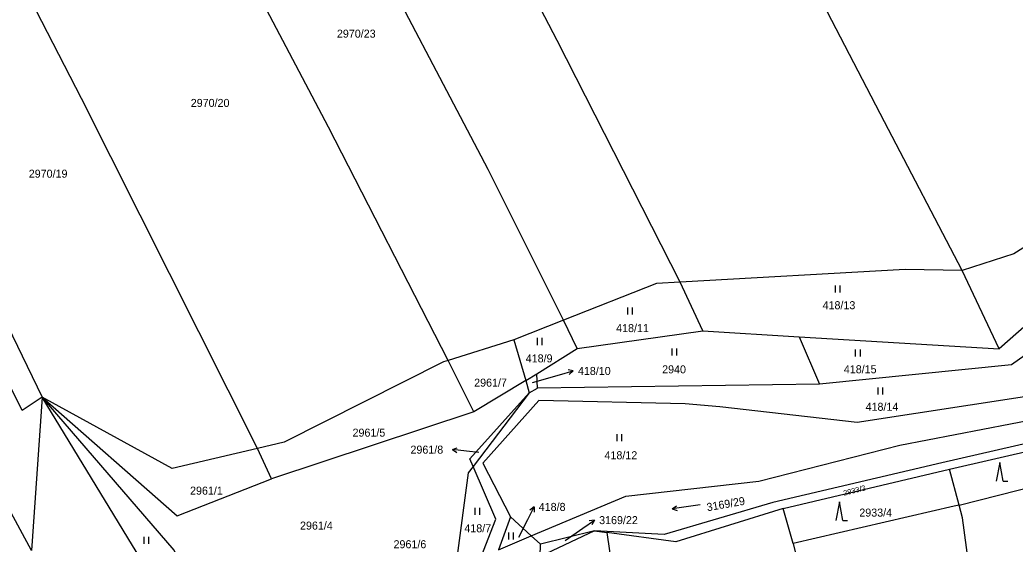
# Model space of a CAD drawing. Extents: x -776734 to -748832, y -1118122 to -976986.
# Drawn here: x -754304.9 to -754093.6, y -1113887.9 to -1113776.6 of the extents above; entities that cross this region are included whole.
import ezdxf

# ---------------------------------------------------------------- set-up
doc = ezdxf.new("R2010")
doc.units = 0
for name, color, linetype in [('KM_Hranice parcel', 7, 'Continuous'), ('KM_Parcelní čísla', 7, 'Continuous'), ('KM_Pop  PČ popisy', 7, 'Continuous'), ('KM_Značky kultur', 7, 'Continuous')]:
    doc.layers.add(name, color=color, linetype=linetype)

msp = doc.modelspace()

# ---------------------------------------------------------------- linework, layer by layer
at = {"layer": 'KM_Hranice parcel'}
for p, q in [((-754318.46, -1113819.03), (-754300.22, -1113856.73)), ((-754097, -1113846.43), (-754104.86, -1113829.84)), ((-754077.8, -1113829.36), (-754097, -1113846.43)), ((-754159.94, -1113842.59), (-754164.76, -1113832.3)), ((-754189.51, -1113840.37), (-754200.04, -1113844.53)), ((-754186.65, -1113846.37), (-754189.51, -1113840.37)), ((-754186.65, -1113846.37), (-754159.94, -1113842.59)), ((-754159.94, -1113842.59), (-754139.48, -1113843.91)), ((-754200.04, -1113844.53), (-754214.04, -1113848.92)), ((-754200.04, -1113844.53), (-754197.55, -1113853.18)), ((-754139.48, -1113843.91), (-754097, -1113846.43)), ((-754139.48, -1113843.91), (-754135.16, -1113853.97)), ((-754195.19, -1113851.76), (-754186.65, -1113846.37)), ((-754208.56, -1113859.8), (-754214.04, -1113848.92)), ((-754197.55, -1113853.18), (-754195.19, -1113851.76)), ((-754195.04, -1113854.77), (-754195.19, -1113851.76)), ((-754197.55, -1113853.18), (-754208.56, -1113859.8)), ((-754197.55, -1113853.18), (-754196.79, -1113855.81)), ((-754135.16, -1113853.97), (-754195.04, -1113854.77)), ((-754196.79, -1113855.81), (-754208.72, -1113871.43)), ((-754196.79, -1113855.81), (-754195.04, -1113854.77)), ((-754300.22, -1113856.73), (-754302.5, -1113889.3)), ((-754274.44, -1113898.95), (-754300.22, -1113856.73)), ((-754208.56, -1113859.8), (-754251.51, -1113874.03)), ((-754107.55, -1113872.02), (-754074.63, -1113864.42)), ((-754302.5, -1113889.3), (-754314.85, -1113866.35)), ((-754251.51, -1113874.03), (-754254.49, -1113867.61)), ((-754142.86, -1113880.35), (-754107.55, -1113872.02)), ((-754105.53, -1113879.61), (-754107.55, -1113872.02)), ((-754105.53, -1113879.61), (-754073.23, -1113871.5)), ((-754140.8, -1113887.79), (-754142.86, -1113880.35)), ((-754200.79, -1113882.1), (-754203.33, -1113889.11)), ((-754196.38, -1113886.18), (-754200.79, -1113882.1)), ((-754182.95, -1113885.07), (-754194.51, -1113890.52)), ((-754182.95, -1113885.07), (-754194.43, -1113887.89)), ((-754182.95, -1113885.07), (-754180.32, -1113885.43)), ((-754180.32, -1113885.43), (-754179.21, -1113893.05)), ((-754203.33, -1113889.11), (-754196.38, -1113886.18)), ((-754194.43, -1113887.89), (-754196.38, -1113886.18)), ((-754140.8, -1113887.79), (-754139.9, -1113891.23)), ((-754194.51, -1113890.52), (-754194.43, -1113887.89))]:
    msp.add_line(p, q, dxfattribs=at)
for points in [[(-754104.86, -1113829.84), (-754121.36, -1113798.21), (-754148.4, -1113746.13), (-754192.53, -1113660.57)], [(-754214.04, -1113848.92), (-754239.4, -1113799.37), (-754268.43, -1113744.24), (-754290.21, -1113702.49)], [(-754164.76, -1113832.3), (-754190.89, -1113781), (-754231.66, -1113702.65)], [(-754189.51, -1113840.37), (-754205.49, -1113808.35), (-754233.36, -1113755.33), (-754259.94, -1113704.24)], [(-754254.49, -1113867.61), (-754291.87, -1113793.3), (-754334.19, -1113711.19)], [(-754300.22, -1113856.73), (-754304.48, -1113859.53), (-754347.97, -1113771.53), (-754351.53, -1113761.63)], [(-754064.58, -1113807.73), (-754093.92, -1113826.24), (-754104.86, -1113829.84)], [(-754104.86, -1113829.84), (-754117, -1113829.63), (-754164.76, -1113832.3)], [(-754164.76, -1113832.3), (-754169.77, -1113832.58), (-754189.51, -1113840.37)], [(-754078.21, -1113838.35), (-754094.44, -1113849.84), (-754135.16, -1113853.97)], [(-754214.04, -1113848.92), (-754215.01, -1113849.22), (-754248.86, -1113866.28), (-754254.49, -1113867.61)], [(-754078.67, -1113848.38), (-754090.72, -1113856.52), (-754127.21, -1113862.08), (-754156.31, -1113858.73), (-754163.7, -1113858.09), (-754194.79, -1113857.45), (-754206.68, -1113870.75), (-754200.79, -1113882.1)], [(-754196.38, -1113886.18), (-754176.31, -1113877.74), (-754148.04, -1113874.54), (-754118.15, -1113866.87), (-754082.91, -1113860.1), (-754078.89, -1113853.29), (-754078.67, -1113848.38)], [(-754208.72, -1113871.43), (-754209.43, -1113869.77), (-754196.79, -1113855.81)], [(-754254.49, -1113867.61), (-754272.6, -1113871.88), (-754300.22, -1113856.73)], [(-754300.22, -1113856.73), (-754271.52, -1113881.91), (-754251.51, -1113874.03)], [(-754267.89, -1113898.43), (-754272.19, -1113889.21), (-754300.22, -1113856.73)], [(-754074.96, -1113862.77), (-754109.23, -1113870.62), (-754145.05, -1113879.1), (-754168.15, -1113885.85), (-754182.95, -1113885.07)], [(-754208.72, -1113871.43), (-754209.75, -1113872.78), (-754212.23, -1113891.37)], [(-754206.99, -1113890.65), (-754203.9, -1113882.6), (-754208.72, -1113871.43)], [(-754142.86, -1113880.35), (-754165.65, -1113887.45), (-754180.32, -1113885.43)], [(-754105.53, -1113879.61), (-754106.55, -1113879.87), (-754140.8, -1113887.79)], [(-754096.25, -1114034.06), (-754094.44, -1113999.4), (-754097.03, -1113949.03), (-754099.96, -1113918.6), (-754104.82, -1113882.3), (-754105.53, -1113879.61)]]:
    msp.add_lwpolyline(points, dxfattribs=at)
at = {"layer": 'KM_Pop  PČ popisy'}
for p, q in [((-754190.35, -1113851.95), (-754187.465, -1113851.123)), ((-754187.465, -1113851.123), (-754188.566, -1113850.918)), ((-754187.465, -1113851.123), (-754188.29, -1113851.88)), ((-754196.11, -1113853.56), (-754190.35, -1113851.95)), ((-754213.125, -1113867.846), (-754212.076, -1113867.453)), ((-754210.14, -1113868.16), (-754213.125, -1113867.846)), ((-754213.125, -1113867.846), (-754212.181, -1113868.449)), ((-754207.5, -1113868.44), (-754210.14, -1113868.16)), ((-754197.12, -1113882.69), (-754195.758, -1113880.016)), ((-754195.758, -1113880.016), (-754196.658, -1113880.681)), ((-754195.758, -1113880.016), (-754195.766, -1113881.136)), ((-754199.01, -1113886.47), (-754197.12, -1113882.69)), ((-754185.41, -1113884.55), (-754182.952, -1113882.829)), ((-754182.952, -1113882.829), (-754184.059, -1113882.993)), ((-754182.952, -1113882.829), (-754183.485, -1113883.813)), ((-754189.15, -1113887.18), (-754185.41, -1113884.55))]:
    msp.add_line(p, q, dxfattribs=at)
at = {"layer": 'KM_Značky kultur'}
for p, q in [((-754131.811, -1113834.48), (-754131.811, -1113832.98)), ((-754130.81, -1113834.48), (-754130.81, -1113832.98)), ((-754175.841, -1113839.15), (-754175.841, -1113837.65)), ((-754174.84, -1113839.15), (-754174.84, -1113837.65)), ((-754195.071, -1113845.63), (-754195.071, -1113844.13)), ((-754194.07, -1113845.63), (-754194.07, -1113844.13)), ((-754166.431, -1113847.89), (-754166.431, -1113846.39)), ((-754165.43, -1113847.89), (-754165.43, -1113846.39)), ((-754127.501, -1113848.09), (-754127.501, -1113846.59)), ((-754126.5, -1113848.09), (-754126.5, -1113846.59)), ((-754122.741, -1113856.14), (-754122.741, -1113854.64)), ((-754121.74, -1113856.14), (-754121.74, -1113854.64)), ((-754178.131, -1113866.05), (-754178.131, -1113864.55)), ((-754177.13, -1113866.05), (-754177.13, -1113864.55)), ((-754096.91, -1113870.56), (-754097.66, -1113874.56)), ((-754096.16, -1113874.56), (-754096.91, -1113870.56)), ((-754096.16, -1113874.56), (-754095.164, -1113874.56)), ((-754130.96, -1113878.9), (-754131.71, -1113882.9)), ((-754130.21, -1113882.9), (-754130.96, -1113878.9)), ((-754208.261, -1113881.71), (-754208.261, -1113880.21)), ((-754207.26, -1113881.71), (-754207.26, -1113880.21)), ((-754160.507, -1113879.586), (-754166.449, -1113880.421)), ((-754166.449, -1113880.421), (-754165.551, -1113879.789)), ((-754166.449, -1113880.421), (-754165.412, -1113880.782)), ((-754130.21, -1113882.9), (-754129.214, -1113882.9)), ((-754201.151, -1113886.93), (-754201.151, -1113885.43)), ((-754200.15, -1113886.93), (-754200.15, -1113885.43)), ((-754278.531, -1113887.85), (-754278.531, -1113886.35)), ((-754277.53, -1113887.85), (-754277.53, -1113886.35))]:
    msp.add_line(p, q, dxfattribs=at)

# ---------------------------------------------------------------- texts
at = {"layer": 'KM_Parcelní čísla'}
for s, p in [('2970/23', (-754237.63, -1113780.36)), ('2970/20', (-754268.66, -1113795.07)), ('2970/19', (-754303.05, -1113810.1)), ('418/13', (-754134.52, -1113838.03)), ('418/11', (-754178.35, -1113842.89)), ('418/9', (-754197.54, -1113849.32)), ('418/10', (-754186.46, -1113851.99)), ('2940', (-754168.58, -1113851.65)), ('418/15', (-754130.01, -1113851.63)), ('2961/7', (-754208.49, -1113854.47)), ('418/14', (-754125.39, -1113859.6)), ('2961/5', (-754234.31, -1113865.09)), ('2961/8', (-754222.015, -1113868.7)), ('418/12', (-754180.82, -1113869.89)), ('2961/1', (-754268.81, -1113877.41)), ('418/8', (-754194.78, -1113880.86)), ('2933/4', (-754126.72, -1113882.07)), ('2961/4', (-754245.46, -1113884.83)), ('3169/22', (-754181.96, -1113883.67)), ('418/7', (-754210.57, -1113885.4)), ('2961/6', (-754225.605, -1113888.79))]:
    msp.add_text(s, height=1.7, dxfattribs=at).set_placement(p)
for s, height, rotation, p in [('2933/3', 1.14, 14, (-754129.96, -1113877.643)), ('3169/29', 1.7, 10, (-754158.972, -1113880.947))]:
    msp.add_text(s, height=height, rotation=rotation, dxfattribs=at).set_placement(p)

doc.saveas('drawing.dxf')
